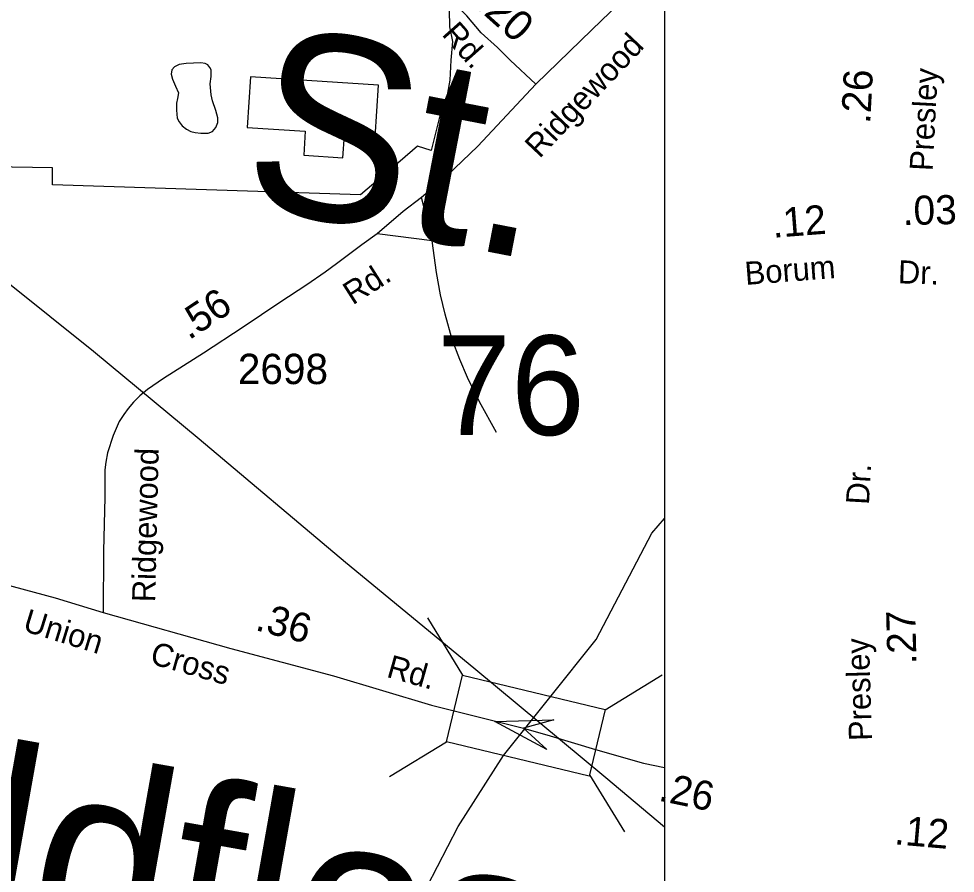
# Model space of a CAD drawing. Extents: x 1553981 to 1780076, y 812965 to 996873.
# Drawn here: x 1636043.1 to 1636525.7, y 845725.2 to 846165.4 of the extents above; entities that cross this region are included whole.
import ezdxf

# ---------------------------------------------------------------- set-up
doc = ezdxf.new("R2010")
doc.units = 0
for name, color, linetype in [('Default', 7, 'Continuous'), ('Exist Cultural Warehouse Building Footprint', 7, 'Continuous'), ('Exist Hydrographic Creek Single Shore', 7, 'Continuous'), ('Exist Hydrographic Misc Water Feature', 7, 'Continuous'), ('Exist Road Non-System Type 51 Label', 7, 'Continuous'), ('Exist Road Secondary Mileage Hundredths English Label', 7, 'Continuous'), ('Exist Road Secondary Structure Standard Bridge Attributed CELL', 7, 'Continuous'), ('Exist Road Secondary Structure Standard Bridge CELL', 7, 'Continuous'), ('Exist Road Secondary Structure Standard Bridge Number Label', 7, 'Continuous'), ('Exist Road Secondary Type 51 Attributed', 7, 'Continuous'), ('Exist Road Secondary Type 51 Number Label', 7, 'Continuous'), ('Exist Utilities Electrical Transmission Line', 7, 'Continuous'), ('Map Preparation Border Antique Large Shape', 7, 'Continuous'), ('Map Preparation Border County Name Lower Right Label', 7, 'Continuous'), ('Map Preparation Border FIPS Code Label', 7, 'Continuous'), ('Map Preparation Border Revised Sign Off', 7, 'Continuous')]:
    doc.layers.add(name, color=color, linetype=linetype)

msp = doc.modelspace()

# ---------------------------------------------------------------- linework, layer by layer
at = {"layer": 'Default'}
msp.add_lwpolyline([(1632323.05, 848155.4), (1636375.85, 848155.4), (1636375.85, 845052.3), (1632323.05, 845052.3)], close=True, dxfattribs=at)
at = {"layer": 'Exist Cultural Warehouse Building Footprint'}
msp.add_lwpolyline([(1636228.53, 846131.14), (1636162.58, 846135.49), (1636160.87, 846109.43), (1636190.75, 846107.46), (1636189.94, 846095.04), (1636210.14, 846093.71), (1636210.91, 846105.5), (1636226.77, 846104.45)], close=True, dxfattribs=at)
at = {"layer": 'Exist Hydrographic Creek Single Shore'}
msp.add_lwpolyline([(1636230, 845663.56), (1636232.25, 845677.05), (1636269.63, 845749.32), (1636293, 845785.78), (1636340.62, 845845.55), (1636369.38, 845900.35), (1636375.85, 845907.95)], dxfattribs=at)
at = {"layer": 'Exist Hydrographic Misc Water Feature'}
msp.add_lwpolyline([(1636125.77, 846141.78), (1636123.42, 846140.69), (1636121.98, 846139.06), (1636121.58, 846136.81), (1636122.37, 846134.25), (1636123.83, 846130.71), (1636125.51, 846127.31), (1636124.95, 846124.24), (1636124.4, 846121.85), (1636124.42, 846118.32), (1636124.68, 846114.2), (1636125.86, 846112.3), (1636127.41, 846110.26), (1636129.56, 846108.58), (1636131.72, 846107.35), (1636133.97, 846106.87), (1636136.96, 846106.38), (1636140.71, 846106.41), (1636143.04, 846107.36), (1636144.65, 846109.36), (1636145.66, 846111.97), (1636145.76, 846114.37), (1636144.75, 846118.06), (1636143.01, 846123.03), (1636142.3, 846126.19), (1636141.84, 846131.82), (1636142.34, 846135.72), (1636142.24, 846139.1), (1636141.65, 846140.23), (1636140.47, 846141.6), (1636139.2, 846142.43), (1636136.88, 846142.61), (1636129.45, 846142.34), (1636125.77, 846141.78)], dxfattribs=at)
at = {"layer": 'Exist Road Secondary Structure Standard Bridge Attributed CELL'}
msp.add_lwpolyline([(1636315.24, 845788.87), (1636288.46, 845803.43), (1636318.93, 845804.21), (1636303.28, 845799.87)], close=True, dxfattribs=at)
at = {"layer": 'Exist Road Secondary Structure Standard Bridge CELL'}
for p, q in [((1636253.82, 845856.68), (1636271.83, 845827.25)), ((1636345.25, 845809.42), (1636374.68, 845827.42)), ((1636234.15, 845774.93), (1636263.58, 845792.94)), ((1636337.18, 845775.88), (1636355.19, 845746.45))]:
    msp.add_line(p, q, dxfattribs=at)
msp.add_lwpolyline([(1636271.83, 845827.25), (1636345.29, 845809.58), (1636337.03, 845775.26), (1636263.58, 845792.94)], close=True, dxfattribs=at)
at = {"layer": 'Exist Road Secondary Type 51 Attributed'}
for points in [[(1636309.55, 846131.72), (1636296.37, 846144.03), (1636289.78, 846150.62), (1636281.44, 846158.1), (1636273.97, 846166.89), (1636264.74, 846176.12), (1636261.23, 846180.07), (1636258.59, 846185.35), (1636255.96, 846192.38), (1636252.44, 846202.49), (1636237.62, 846238.94)], [(1636375.85, 846195.88), (1636338.36, 846159.74), (1636309.55, 846131.72)], [(1636309.55, 846131.72), (1636279.61, 846099.81), (1636263.79, 846084.4), (1636250.73, 846073.23), (1636241.2, 846066.05), (1636227.89, 846054.64), (1636219.87, 846048.92), (1636213.08, 846043.73), (1636206.81, 846039.06), (1636201.05, 846034.8), (1636191.51, 846028.36), (1636177.74, 846019.19), (1636158.68, 846006.57), (1636138.37, 845993.17), (1636117.79, 845980.06), (1636109.52, 845974.35), (1636105.5, 845971.13), (1636102.24, 845967.89), (1636099.47, 845964.67), (1636097.2, 845961.44), (1636094.93, 845957.96), (1636091.83, 845950.65), (1636088.85, 845941.75), (1636087.93, 845936.99), (1636087.54, 845933), (1636087.46, 845918.99), (1636086.79, 845891.02), (1636086.63, 845859.53)], [(1635929.89, 845876.75), (1635957.61, 845880.75), (1635975.91, 845881.89), (1635995.59, 845882.35), (1636007.61, 845881.67), (1636061.96, 845867.07), (1636086.63, 845859.53)], [(1636086.63, 845859.53), (1636152.46, 845840.88), (1636205.33, 845826.82), (1636255.82, 845811.74), (1636303.28, 845799.87)], [(1636303.28, 845799.87), (1636316.97, 845795.95), (1636340.38, 845788.98), (1636365.05, 845781.86), (1636375.85, 845779.68)]]:
    msp.add_lwpolyline(points, dxfattribs=at)
at = {"layer": 'Exist Utilities Electrical Transmission Line'}
msp.add_lwpolyline([(1636375.85, 845748.85), (1636345.66, 845774.27), (1636277.7, 845830.91), (1636211.42, 845885.26), (1636136.04, 845948.75), (1636081.65, 845993.95), (1636036.64, 846030.01), (1635968.17, 846087.65), (1635879.95, 846163.04), (1635816.18, 846216.36), (1635751.9, 846269.69), (1635687.64, 846323.53), (1635627.31, 846373.05), (1635562.54, 846428.15), (1635495.06, 846483.5), (1635443.89, 846525.91), (1635382.59, 846577.96), (1635322.52, 846628.98), (1635266.9, 846675.21)], dxfattribs=at)
at = {"layer": 'Map Preparation Border County Name Lower Right Label'}
msp.add_line((1636256.1, 846050.96), (1636227.89, 846054.64), dxfattribs=at)
for points in [[(1636256.1, 846050.96), (1636253.16, 846063.31), (1636250.73, 846073.23)], [(1636289.24, 845952.29), (1636280.58, 845968.1), (1636274.43, 845980.63), (1636270.47, 845989.89), (1636266.55, 846000.17), (1636262.86, 846013.18), (1636260.44, 846023.19), (1636258.45, 846034.63), (1636256.1, 846050.96)]]:
    msp.add_lwpolyline(points, dxfattribs=at)
at = {"layer": 'Map Preparation Border FIPS Code Label'}
msp.add_lwpolyline([(1636264.9, 846169.97), (1636265.02, 846161.21), (1636266.58, 846153.62), (1636265.8, 846144.01), (1636265.3, 846133.83), (1636263.67, 846125.19), (1636259.85, 846113.97), (1636255.71, 846097.6), (1636248.56, 846099.81), (1636239.64, 846092.03), (1636219.17, 846074.72), (1636060.51, 846079.82), (1636060.58, 846088.57), (1636029.32, 846089.12)], dxfattribs=at)
at = {"layer": 'Map Preparation Border Revised Sign Off'}
msp.add_lwpolyline([(1636264.9, 846169.97), (1636265.02, 846161.21), (1636266.58, 846153.62), (1636265.8, 846144.01), (1636265.3, 846133.83), (1636263.67, 846125.19), (1636259.85, 846113.97), (1636255.71, 846097.6), (1636248.56, 846099.81), (1636239.64, 846092.03), (1636219.17, 846074.72), (1636060.51, 846079.82), (1636060.58, 846088.57), (1636029.32, 846089.12)], dxfattribs=at)

# ---------------------------------------------------------------- texts
at = {"layer": 'Exist Road Non-System Type 51 Label'}
for s, rotation, p in [('St.', 349.0456, (1636155.65, 846070.4)), ('Goldfloss', 349.9055, (1635849.89, 845727.02))]:
    msp.add_text(s, height=95, rotation=rotation, dxfattribs=at).set_placement(p)
at = {"layer": 'Exist Road Secondary Mileage Hundredths English Label'}
for s, height, rotation, p in [('.20', 15.625, 318.1625, (1636277.92, 846171.73)), ('.26', 15, 87.0056, (1636481.88, 846111.09)), ('.03', 15, 1.1468, (1636498.77, 846059.09)), ('.12', 15, 4.4226, (1636431.86, 846052.53)), ('.56', 15, 33.4997, (1636130.82, 845999.63)), ('.36', 15, 345.1108, (1636164.47, 845850.57)), ('.27', 15, 91.4945, (1636505.79, 845832.87)), ('.26', 15, 348.2792, (1636372.32, 845762.68)), ('.12', 15, 355.021, (1636494.01, 845740.14))]:
    msp.add_text(s, height=height, rotation=rotation, dxfattribs=at).set_placement(p)
at = {"layer": 'Exist Road Secondary Structure Standard Bridge Number Label'}
msp.add_text('76', height=51.263, dxfattribs=at).set_placement((1636258.6, 845950.96))
at = {"layer": 'Exist Road Secondary Type 51 Number Label'}
msp.add_text('2698', height=15.625, dxfattribs=at).set_placement((1636156.02, 845977.18))
at = {"layer": 'Map Preparation Border Antique Large Shape'}
for s, rotation, p in [('Rd.', 311.6393, (1636260.72, 846157.2)), ('Ridgewood', 46.7012, (1636311.5, 846093.08)), ('Presley', 87.0056, (1636514.04, 846086.76)), ('Rd.', 32.5106, (1636215.19, 846017.66)), ('Borum', 4.4226, (1636417.69, 846028.25)), ('Dr.', 358.0705, (1636496.06, 846029.13)), ('Ridgewood', 88.6312, (1636113.37, 845864.71)), ('Dr.', 86.7136, (1636481.23, 845914.82)), ('Union', 342.8954, (1636044.67, 845850.22)), ('Presley', 91.7481, (1636482.84, 845793.53)), ('Cross', 344.1853, (1636110.18, 845833.32)), ('Rd.', 344.1853, (1636232.15, 845826.43))]:
    msp.add_text(s, height=11.875, rotation=rotation, dxfattribs=at).set_placement(p)

doc.saveas('drawing.dxf')
